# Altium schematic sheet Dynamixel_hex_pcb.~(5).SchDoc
size 297 x 209 mm
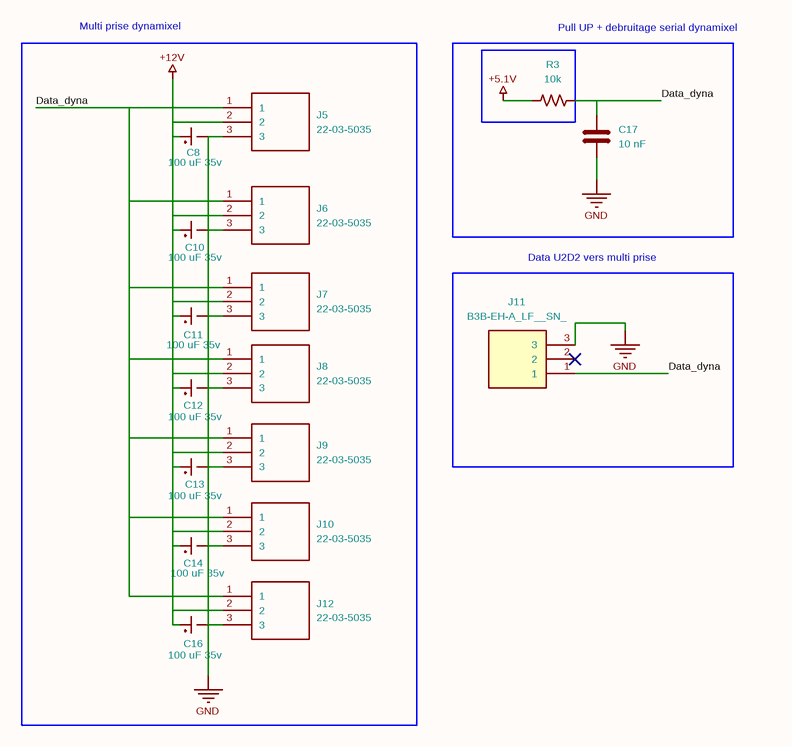
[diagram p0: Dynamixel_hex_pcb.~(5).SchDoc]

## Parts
C8  100 uF 35v  [CP_Wurth_WCAP-HSG5-D6.3L7.7]
C10  100 uF 35v  [CP_Wurth_WCAP-HSG5-D6.3L7.7]
C11  100 uF 35v  [CP_Wurth_WCAP-HSG5-D6.3L7.7]
C12  100 uF 35v  [CP_Wurth_WCAP-HSG5-D6.3L7.7]
C13  100 uF 35v  [CP_Wurth_WCAP-HSG5-D6.3L7.7]
C14  100 uF 35v  [CP_Wurth_WCAP-HSG5-D6.3L7.7]
C16  100 uF 35v  [CP_Wurth_WCAP-HSG5-D6.3L7.7]
C17  10 nF  [C_0603_1608Metric]
J5  22-03-5035  [Molex_SPOX_5267-03A_1x03_P2.50mm_Vertical]
J6  22-03-5035  [Molex_SPOX_5267-03A_1x03_P2.50mm_Vertical]
J7  22-03-5035  [Molex_SPOX_5267-03A_1x03_P2.50mm_Vertical]
J8  22-03-5035  [Molex_SPOX_5267-03A_1x03_P2.50mm_Vertical]
J9  22-03-5035  [Molex_SPOX_5267-03A_1x03_P2.50mm_Vertical]
J10  22-03-5035  [Molex_SPOX_5267-03A_1x03_P2.50mm_Vertical]
J11  B3B-EH-A_LF__SN_  [JST_EH_B3B-EH-A_1x03_P2.50mm_Vertical]
J12  22-03-5035  [Molex_SPOX_5267-03A_1x03_P2.50mm_Vertical]
R3  10k  [R_0201_0603Metric]

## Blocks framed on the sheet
Multi prise dynamixel: C8 C10-C14 C16 J5-J10 J12
Pull UP + debruitage serial dynamixel: R3
Data U2D2 vers multi prise: J11

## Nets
+5.1V: R3.1
+12V: C8.1 C10.1 C11.1 C12.1 C13.1 C14.1 C16.1 J5.2 J6.2 J7.2 J8.2 J9.2 J10.2 J12.2
GND: C8.2 C10.2 C11.2 C12.2 C13.2 C14.2 C16.2 C17.2 J5.3 J6.3 J7.3 J8.3 J9.3 J10.3 J11.3 J12.3
Data_dyna: C17.1 J5.1 J6.1 J7.1 J8.1 J9.1 J10.1 J11.1 J12.1 R3.2

Not connected (* = marked no-connect by the designer): J11 2*

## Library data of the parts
C8 C10-C14 C16 = C_Polarized_Small_US: Description: Polarized capacitor, small US symbol
C17 = C: Description: Unpolarized capacitor
J5-J10 J12 = 22-03-5035: Manufacturer_Name: Molex; Description: Header 2.5mm SPOX,WTB,vert, shrouded, 3w Molex SPOX Series, Series Number 5267, 2.5mm Pitch 3 Way 1 Row Straight PCB Header, Solder Termination, 3A
J11 = B3B-EH-A_LF__SN_: Manufacturer_Name: JST (JAPAN SOLDERLESS TERMINALS); Manufacturer_Part_Number: B3B-EH-A(LF)(SN); Description: JST (JAPAN SOLDERLESS TERMINALS) - B3B-EH-A(LF)(SN) - CONNECTOR, HEADER, 3POS, 2.5MM, 1ROW
R3 = R_US: Description: Resistor, US symbol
